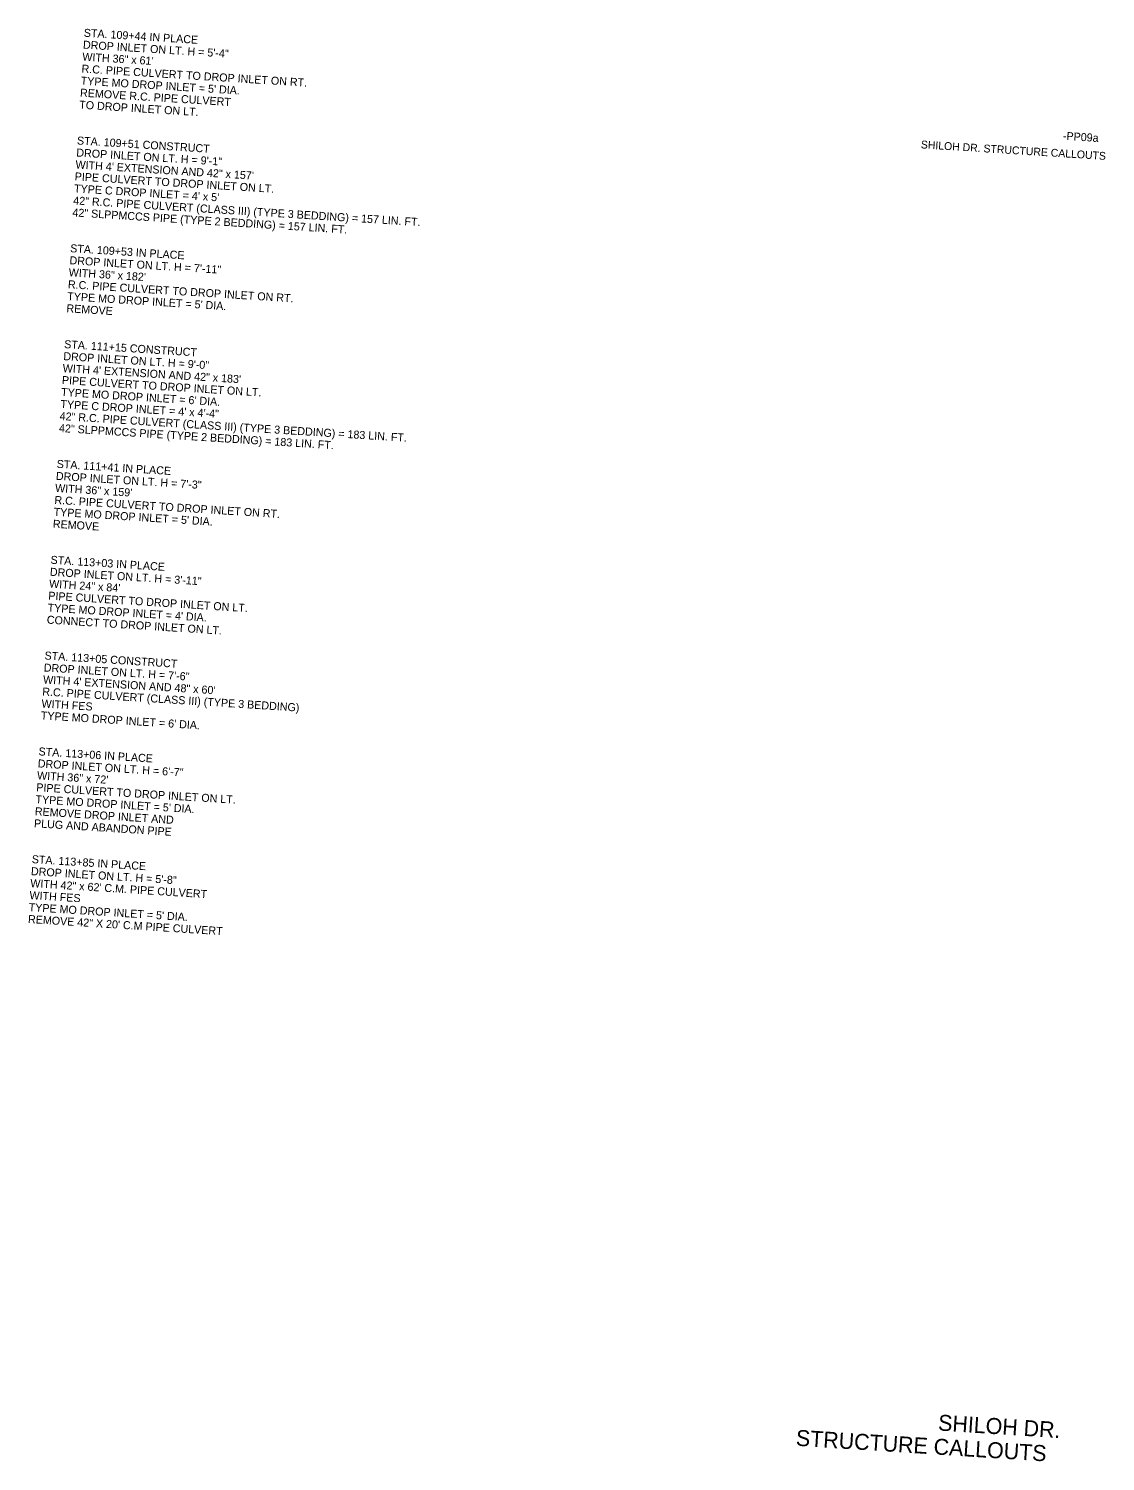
# Model space of a CAD drawing. Extents: x 660731 to 669183, y 641696 to 736523.
# Drawn here: x 661499 to 662306, y 641696 to 642771 of the extents above; entities that cross this region are included whole.
import ezdxf

# ---------------------------------------------------------------- set-up
doc = ezdxf.new("R2010")
doc.units = 0
for name, color, linetype in [('R_Axis', 7, 'Continuous'), ('R_Erosion', 7, 'Continuous'), ('T_Indications', 7, 'Continuous')]:
    doc.layers.add(name, color=color, linetype=linetype)

msp = doc.modelspace()

# ---------------------------------------------------------------- texts
at = {"layer": 'R_Axis'}
for s, height, p in [('-PP09a', 6, (662274.1, 642687.5)), ('SHILOH DR. STRUCTURE CALLOUTS', 5.862, (662167.6, 642681.1))]:
    msp.add_text(s, height=height, rotation=356.3979, dxfattribs=at).set_placement(p)
at = {"layer": 'R_Erosion'}
for s, p in [('SHILOH DR.', (662180.4, 641719.6)), ('STRUCTURE CALLOUTS', (662073.8, 641708.2))]:
    msp.add_text(s, height=12, rotation=356.3979, dxfattribs=at).set_placement(p)
at = {"layer": 'T_Indications'}
for s, p in [('STA. 109+44 IN PLACE', (661540.1, 642764.8)), ('DROP INLET ON LT. H = 5\'-4"', (661539.5, 642755.9)), ('WITH 36" x 61\'', (661539, 642746.9)), ('R.C. PIPE CULVERT TO DROP INLET ON RT.', (661538.4, 642737.9)), ('REMOVE R.C. PIPE CULVERT', (661537.3, 642719.9)), ("TYPE MO DROP INLET = 5' DIA.", (661537.8, 642728.9)), ('TO DROP INLET ON LT.', (661536.7, 642710.9)), ('STA. 109+51 CONSTRUCT', (661535, 642684)), ('WITH 4\' EXTENSION AND 42" x 157\'', (661533.9, 642666)), ('DROP INLET ON LT. H = 9\'-1"', (661534.5, 642675)), ('PIPE CULVERT TO DROP INLET ON LT.', (661533.3, 642657.1)), ("TYPE C DROP INLET = 4' x 5'", (661532.8, 642648.1)), ('42" R.C. PIPE CULVERT (CLASS III) (TYPE 3 BEDDING) = 157 LIN. FT.', (661532.2, 642639.1)), ('42" SLPPMCCS PIPE (TYPE 2 BEDDING) = 157 LIN. FT.', (661531.6, 642630.1)), ('STA. 109+53 IN PLACE', (661529.9, 642603.2)), ('DROP INLET ON LT. H = 7\'-11"', (661529.4, 642594.2)), ('WITH 36" x 182\'', (661528.8, 642585.2)), ('R.C. PIPE CULVERT TO DROP INLET ON RT.', (661528.2, 642576.2)), ('REMOVE', (661527.1, 642558.2)), ("TYPE MO DROP INLET = 5' DIA.", (661527.7, 642567.2)), ('STA. 111+15 CONSTRUCT', (661525.4, 642531.3)), ('DROP INLET ON LT. H = 9\'-0"', (661524.8, 642522.3)), ('PIPE CULVERT TO DROP INLET ON LT.', (661523.7, 642504.4)), ('WITH 4\' EXTENSION AND 42" x 183\'', (661524.3, 642513.3)), ("TYPE MO DROP INLET = 6' DIA.", (661523.1, 642495.4)), ('TYPE C DROP INLET = 4\' x 4\'-4"', (661522.6, 642486.4)), ('42" R.C. PIPE CULVERT (CLASS III) (TYPE 3 BEDDING) = 183 LIN. FT.', (661522, 642477.4)), ('42" SLPPMCCS PIPE (TYPE 2 BEDDING) = 183 LIN. FT.', (661521.5, 642468.4)), ('STA. 111+41 IN PLACE', (661519.8, 642441.5)), ('DROP INLET ON LT. H = 7\'-3"', (661519.2, 642432.5)), ('WITH 36" x 159\'', (661518.6, 642423.5)), ('R.C. PIPE CULVERT TO DROP INLET ON RT.', (661518.1, 642414.5)), ("TYPE MO DROP INLET = 5' DIA.", (661517.5, 642405.6)), ('REMOVE', (661516.9, 642396.6)), ('STA. 113+03 IN PLACE', (661515.2, 642369.6)), ('DROP INLET ON LT. H = 3\'-11"', (661514.7, 642360.6)), ('WITH 24" x 84\'', (661514.1, 642351.7)), ("TYPE MO DROP INLET = 4' DIA.", (661513, 642333.7)), ('PIPE CULVERT TO DROP INLET ON LT.', (661513.5, 642342.7)), ('CONNECT TO DROP INLET ON LT.', (661512.4, 642324.7)), ('STA. 113+05 CONSTRUCT', (661510.7, 642297.8)), ('WITH 4\' EXTENSION AND 48" x 60\'', (661509.6, 642279.8)), ('DROP INLET ON LT. H = 7\'-6"', (661510.1, 642288.8)), ('R.C. PIPE CULVERT (CLASS III) (TYPE 3 BEDDING)', (661509, 642270.8)), ('WITH FES', (661508.4, 642261.8)), ("TYPE MO DROP INLET = 6' DIA.", (661507.9, 642252.9)), ('STA. 113+06 IN PLACE', (661506.2, 642225.9)), ('DROP INLET ON LT. H = 6\'-7"', (661505.6, 642216.9)), ('WITH 36" x 72\'', (661505.1, 642207.9)), ('PIPE CULVERT TO DROP INLET ON LT.', (661504.5, 642199)), ("TYPE MO DROP INLET = 5' DIA.", (661503.9, 642190)), ('PLUG AND ABANDON PIPE', (661502.8, 642172)), ('REMOVE DROP INLET AND', (661503.4, 642181)), ('STA. 113+85 IN PLACE', (661501.1, 642145.1)), ('DROP INLET ON LT. H = 5\'-8"', (661500.5, 642136.1)), ('WITH FES', (661499.4, 642118.1)), ('WITH 42" x 62\' C.M. PIPE CULVERT', (661500, 642127.1)), ("TYPE MO DROP INLET = 5' DIA.", (661498.8, 642109.1)), ('REMOVE 42" X 20\' C.M PIPE CULVERT', (661498.3, 642100.2))]:
    msp.add_text(s, height=6, rotation=356.3979, dxfattribs=at).set_placement(p)

doc.saveas('drawing.dxf')
